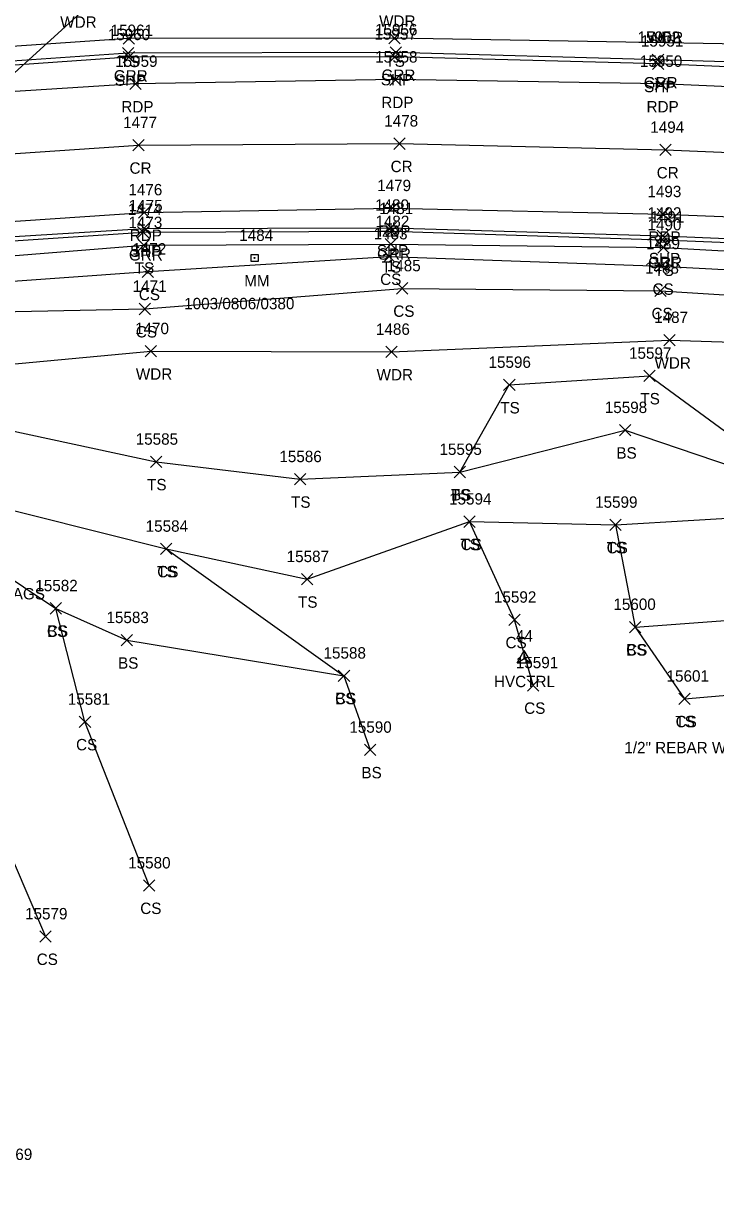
# Model space of a CAD drawing. Extents: x 1606530 to 1613020, y 784959 to 789666.
# Drawn here: x 1609266.7 to 1609388.2, y 788263.1 to 788467.6 of the extents above; entities that cross this region are included whole.
import ezdxf

# ---------------------------------------------------------------- set-up
doc = ezdxf.new("R2010")
doc.units = 0
for name, color, linetype in [('C_A', 7, 'Continuous'), ('C_I', 7, 'Continuous'), ('CPSM', 7, 'Continuous'), ('DCP', 7, 'Continuous'), ('L_A', 7, 'Continuous'), ('L_I', 7, 'Continuous'), ('L_TIC', 7, 'Continuous'), ('LAWA', 7, 'Continuous'), ('LELB', 7, 'Continuous'), ('M_C', 7, 'Continuous'), ('P_A', 7, 'Continuous'), ('P_I', 7, 'Continuous'), ('P_TIC', 7, 'Continuous'), ('PET', 7, 'Continuous'), ('PRC', 7, 'Continuous'), ('PSP', 7, 'Continuous'), ('R_A', 7, 'Continuous'), ('R_I', 7, 'Continuous'), ('R_TIC', 7, 'Continuous'), ('RGR', 7, 'Continuous'), ('S_A', 7, 'Continuous'), ('S_C', 7, 'Continuous'), ('S_I', 7, 'Continuous'), ('SRM', 7, 'Continuous')]:
    doc.layers.add(name, color=color, linetype=linetype)

msp = doc.modelspace()

# ---------------------------------------------------------------- linework, layer by layer
at = {"layer": 'CPSM'}
for p, q in [((1609353.34, 788355.35), (1609354.59, 788357.51)), ((1609355.84, 788355.35), (1609354.59, 788357.51)), ((1609354.59, 788356.07), (1609354.59, 788357.51)), ((1609353.34, 788355.35), (1609354.59, 788356.07)), ((1609353.34, 788355.35), (1609355.84, 788355.35)), ((1609354.59, 788356.07), (1609354.59, 788356.07)), ((1609354.59, 788356.07), (1609355.84, 788355.35))]:
    msp.add_line(p, q, dxfattribs=at)
at = {"layer": 'DCP'}
msp.add_lwpolyline([(1609180.84, 788382.35), (1609291.93, 788483.27)], dxfattribs=at)
at = {"layer": 'L_TIC'}
for points in [[(1609284.23, 788463.87), (1609286.23, 788465.87)], [(1609286.23, 788463.87), (1609284.23, 788465.87)], [(1609330.82, 788463.93), (1609332.82, 788465.93)], [(1609332.82, 788463.93), (1609330.82, 788465.93)], [(1609286.83, 788427.62), (1609288.83, 788429.62)], [(1609288.83, 788427.62), (1609286.83, 788429.62)], [(1609330.16, 788427.8), (1609332.16, 788429.8)], [(1609332.16, 788427.8), (1609330.16, 788429.8)], [(1609378, 788427.23), (1609380, 788429.23)], [(1609380, 788427.23), (1609378, 788429.23)], [(1609329.87, 788425.64), (1609331.87, 788427.64)], [(1609331.87, 788425.64), (1609329.87, 788427.64)], [(1609287.52, 788422.98), (1609289.52, 788424.98)], [(1609289.52, 788422.98), (1609287.52, 788424.98)], [(1609377.66, 788423.92), (1609379.66, 788425.92)], [(1609379.66, 788423.92), (1609377.66, 788425.92)], [(1609332.16, 788420.05), (1609334.16, 788422.05)], [(1609334.16, 788420.05), (1609332.16, 788422.05)], [(1609377.48, 788419.63), (1609379.48, 788421.63)], [(1609379.48, 788419.63), (1609377.48, 788421.63)], [(1609287, 788416.43), (1609289, 788418.43)], [(1609289, 788416.43), (1609287, 788418.43)], [(1609379.07, 788410.97), (1609381.07, 788412.97)], [(1609381.07, 788410.97), (1609379.07, 788412.97)], [(1609288.08, 788409.02), (1609290.08, 788411.02)], [(1609290.08, 788409.02), (1609288.08, 788411.02)], [(1609330.31, 788408.89), (1609332.31, 788410.89)], [(1609332.31, 788408.89), (1609330.31, 788410.89)], [(1609375.56, 788404.69), (1609377.56, 788406.69)], [(1609377.56, 788404.69), (1609375.56, 788406.69)], [(1609350.97, 788403.1), (1609352.97, 788405.1)], [(1609352.97, 788403.1), (1609350.97, 788405.1)], [(1609371.31, 788395.17), (1609373.31, 788397.17)], [(1609373.31, 788395.17), (1609371.31, 788397.17)], [(1609289, 788389.61), (1609291, 788391.61)], [(1609291, 788389.61), (1609289, 788391.61)], [(1609342.3, 788387.82), (1609344.3, 788389.82)], [(1609344.3, 788387.82), (1609342.3, 788389.82)], [(1609342.3, 788387.82), (1609344.3, 788389.82)], [(1609344.3, 788387.82), (1609342.3, 788389.82)], [(1609314.27, 788386.55), (1609316.27, 788388.55)], [(1609316.27, 788386.55), (1609314.27, 788388.55)], [(1609343.99, 788379.11), (1609345.99, 788381.11)], [(1609345.99, 788379.11), (1609343.99, 788381.11)], [(1609343.99, 788379.11), (1609345.99, 788381.11)], [(1609345.99, 788379.11), (1609343.99, 788381.11)], [(1609369.61, 788378.55), (1609371.61, 788380.55)], [(1609371.61, 788378.55), (1609369.61, 788380.55)], [(1609369.61, 788378.55), (1609371.61, 788380.55)], [(1609371.61, 788378.55), (1609369.61, 788380.55)], [(1609290.75, 788374.34), (1609292.75, 788376.34)], [(1609292.75, 788374.34), (1609290.75, 788376.34)], [(1609290.75, 788374.34), (1609292.75, 788376.34)], [(1609292.75, 788374.34), (1609290.75, 788376.34)], [(1609315.49, 788369.01), (1609317.49, 788371.01)], [(1609317.49, 788369.01), (1609315.49, 788371.01)], [(1609271.39, 788363.9), (1609273.39, 788365.9)], [(1609273.39, 788363.9), (1609271.39, 788365.9)], [(1609271.39, 788363.9), (1609273.39, 788365.9)], [(1609273.39, 788363.9), (1609271.39, 788365.9)], [(1609351.86, 788361.89), (1609353.86, 788363.89)], [(1609353.86, 788361.89), (1609351.86, 788363.89)], [(1609373.03, 788360.62), (1609375.03, 788362.62)], [(1609375.03, 788360.62), (1609373.03, 788362.62)], [(1609373.03, 788360.62), (1609375.03, 788362.62)], [(1609375.03, 788360.62), (1609373.03, 788362.62)], [(1609283.87, 788358.31), (1609285.87, 788360.31)], [(1609285.87, 788358.31), (1609283.87, 788360.31)], [(1609321.96, 788352.08), (1609323.96, 788354.08)], [(1609323.96, 788352.08), (1609321.96, 788354.08)], [(1609321.96, 788352.08), (1609323.96, 788354.08)], [(1609323.96, 788352.08), (1609321.96, 788354.08)], [(1609355.14, 788350.39), (1609357.14, 788352.39)], [(1609357.14, 788350.39), (1609355.14, 788352.39)], [(1609381.71, 788348.03), (1609383.71, 788350.03)], [(1609383.71, 788348.03), (1609381.71, 788350.03)], [(1609381.71, 788348.03), (1609383.71, 788350.03)], [(1609383.71, 788348.03), (1609381.71, 788350.03)], [(1609276.51, 788343.98), (1609278.51, 788345.98)], [(1609278.51, 788343.98), (1609276.51, 788345.98)], [(1609326.57, 788339.07), (1609328.57, 788341.07)], [(1609328.57, 788339.07), (1609326.57, 788341.07)], [(1609287.77, 788315.26), (1609289.77, 788317.26)], [(1609289.77, 788315.26), (1609287.77, 788317.26)], [(1609269.6, 788306.32), (1609271.6, 788308.32)], [(1609271.6, 788306.32), (1609269.6, 788308.32)]]:
    msp.add_lwpolyline(points, dxfattribs=at)
at = {"layer": 'LAWA'}
msp.add_lwpolyline([(1609030.56, 788292.64), (1609056.03, 788324.44), (1609082.56, 788354.61), (1609090.16, 788369.42), (1609097.26, 788381.32), (1609109.23, 788386.03), (1609115.48, 788389.16), (1609124.65, 788392.27), (1609168.82, 788397.24), (1609199.02, 788403.22), (1609247.62, 788406.18), (1609289.08, 788410.02), (1609331.31, 788409.89), (1609380.07, 788411.97), (1609422.47, 788410.64), (1609441.9, 788412.64), (1609456.94, 788393.19), (1609459.97, 788389.84), (1609451.94, 788379.3), (1609445.61, 788371.6)], dxfattribs=at)
at = {"layer": 'LELB'}
for points in [[(1609570.41, 788453.62), (1609564.76, 788453.01), (1609526.4, 788455.39), (1609486.04, 788457.71), (1609468.83, 788462.11), (1609453.21, 788464.39), (1609423.17, 788463.36), (1609331.82, 788464.93), (1609285.23, 788464.87), (1609232.95, 788461.35), (1609187.32, 788454.57)], [(1608830.7, 788263.06), (1608870.16, 788285.39), (1608903.61, 788303.66), (1608913.17, 788310.86), (1608944.69, 788327.51), (1608982.09, 788348.33), (1609025.65, 788367.84), (1609062.43, 788383.44), (1609080.36, 788388.45), (1609093.56, 788391.85), (1609111.49, 788398.34), (1609124.29, 788403.55), (1609165.33, 788413.89), (1609196.53, 788419.38), (1609241.91, 788424.94), (1609287.83, 788428.62), (1609331.16, 788428.8), (1609379, 788428.23), (1609424.69, 788425.72), (1609443.9, 788424.45), (1609475.84, 788418.57), (1609486.48, 788419.99), (1609502.63, 788421.7)], [(1609108.11, 788392.39), (1609124.69, 788397.48), (1609165.9, 788409.88), (1609197.34, 788410.75), (1609242.01, 788420.69), (1609288.52, 788423.98), (1609330.87, 788426.64), (1609378.66, 788424.92), (1609423.8, 788422.52), (1609442.79, 788421.03), (1609475.94, 788416.79), (1609485.22, 788416.48)], [(1609199.02, 788403.22), (1609245.4, 788416.55), (1609288, 788417.43), (1609333.16, 788421.05), (1609378.48, 788420.63), (1609422.35, 788417.84)], [(1609229.47, 788383.53), (1609235.87, 788391.77), (1609234.95, 788395.09), (1609256.53, 788397.81), (1609290, 788390.61), (1609315.27, 788387.55), (1609343.3, 788388.82), (1609351.97, 788404.1), (1609376.56, 788405.69), (1609392.36, 788394.13), (1609429.62, 788393.16), (1609442.68, 788388.57), (1609459.97, 788389.84), (1609474.42, 788390.35), (1609486.77, 788400.06), (1609484.73, 788410.56), (1609507.1, 788413.97), (1609507.85, 788418.71)], [(1609343.3, 788388.82), (1609372.31, 788396.17), (1609397.47, 788387.65), (1609429.62, 788393.16)], [(1609235.87, 788391.77), (1609256.08, 788384.31), (1609291.75, 788375.34), (1609316.49, 788370.01), (1609344.99, 788380.11), (1609370.61, 788379.55), (1609398.08, 788381.21), (1609428.47, 788380.83), (1609442.68, 788388.57)], [(1609222.59, 788380.4), (1609229.47, 788383.53), (1609244.73, 788362.88), (1609259.19, 788333.87), (1609270.6, 788307.32)], [(1609229.47, 788383.53), (1609255.52, 788376.15), (1609272.39, 788364.9), (1609284.87, 788359.31), (1609322.96, 788353.08), (1609327.57, 788340.07)], [(1609356.14, 788351.39), (1609352.86, 788362.89), (1609344.99, 788380.11)], [(1609370.61, 788379.55), (1609374.03, 788361.62), (1609382.71, 788349.03)], [(1609291.75, 788375.34), (1609322.96, 788353.08)], [(1609374.03, 788361.62), (1609409.62, 788364.21), (1609429.2, 788364.13), (1609464.94, 788364.57), (1609503.84, 788368.43), (1609529.95, 788369.13)], [(1609382.71, 788349.03), (1609409.78, 788351.37), (1609431.66, 788354.24), (1609466.67, 788360.22), (1609502.72, 788364.36), (1609529.95, 788369.13)], [(1609288.77, 788316.26), (1609277.51, 788344.98), (1609272.39, 788364.9)]]:
    msp.add_lwpolyline(points, dxfattribs=at)
at = {"layer": 'P_TIC'}
for points in [[(1609284.23, 788460.6), (1609286.23, 788462.6)], [(1609286.23, 788460.6), (1609284.23, 788462.6)], [(1609330.88, 788460.68), (1609332.88, 788462.68)], [(1609332.88, 788460.68), (1609330.88, 788462.68)], [(1609377.09, 788459.47), (1609379.09, 788461.47)], [(1609379.09, 788459.47), (1609377.09, 788461.47)], [(1609285.4, 788455.92), (1609287.4, 788457.92)], [(1609287.4, 788455.92), (1609285.4, 788457.92)], [(1609331.01, 788456.67), (1609333.01, 788458.67)], [(1609333.01, 788456.67), (1609331.01, 788458.67)], [(1609377.56, 788455.92), (1609379.56, 788457.92)], [(1609379.56, 788455.92), (1609377.56, 788457.92)], [(1609285.9, 788445.16), (1609287.9, 788447.16)], [(1609287.9, 788445.16), (1609285.9, 788447.16)], [(1609331.71, 788445.44), (1609333.71, 788447.44)], [(1609333.71, 788445.44), (1609331.71, 788447.44)], [(1609378.39, 788444.34), (1609380.39, 788446.34)], [(1609380.39, 788444.34), (1609378.39, 788446.34)], [(1609286.88, 788433.37), (1609288.88, 788435.37)], [(1609288.88, 788433.37), (1609286.88, 788435.37)], [(1609330.48, 788434.11), (1609332.48, 788436.11)], [(1609332.48, 788434.11), (1609330.48, 788436.11)], [(1609377.89, 788433.05), (1609379.89, 788435.05)], [(1609379.89, 788433.05), (1609377.89, 788435.05)], [(1609286.88, 788430.58), (1609288.88, 788432.58)], [(1609288.88, 788430.58), (1609286.88, 788432.58)], [(1609330.2, 788430.67), (1609332.2, 788432.67)], [(1609332.2, 788430.67), (1609330.2, 788432.67)], [(1609377.92, 788429.28), (1609379.92, 788431.28)], [(1609379.92, 788429.28), (1609377.92, 788431.28)]]:
    msp.add_lwpolyline(points, dxfattribs=at)
at = {"layer": 'PET'}
for points in [[(1609713.17, 788438.63), (1609680.93, 788440.45), (1609652, 788442.02), (1609625.85, 788443.73), (1609580.96, 788446.42), (1609565.08, 788447.47), (1609525.71, 788449.46), (1609486.16, 788451.54), (1609451.91, 788453.58), (1609423.87, 788454.94), (1609378.56, 788456.92), (1609332.01, 788457.67), (1609286.4, 788456.92), (1609233.03, 788453.52), (1609189.08, 788447.38), (1609175.76, 788445.19), (1609148.78, 788440), (1609127.71, 788434.8)], [(1608827.2, 788266.24), (1608867.86, 788290.54), (1608906.68, 788312.86), (1608942.68, 788332.75), (1608980.54, 788352.16), (1609023.57, 788373.22), (1609061.44, 788389.9), (1609090.8, 788401.17), (1609121.92, 788410.09), (1609165.17, 788420), (1609195.85, 788425.54), (1609240.14, 788431.13), (1609287.88, 788434.37), (1609331.48, 788435.11), (1609378.89, 788434.05), (1609425.43, 788432.25), (1609443.83, 788431.33), (1609477.32, 788429.78), (1609518.44, 788427.6), (1609569.18, 788424.68), (1609602.99, 788422.58), (1609641.45, 788420.37), (1609681.7, 788417.92), (1609727.38, 788415.53)]]:
    msp.add_lwpolyline(points, dxfattribs=at)
at = {"layer": 'PRC'}
msp.add_lwpolyline([(1608863.25, 788300.9), (1608901.81, 788322.6), (1608937.61, 788342.72), (1608976.12, 788362.76), (1609017.58, 788382.95), (1609062.58, 788402.24), (1609089.79, 788412.89), (1609118.81, 788421.44), (1609162.84, 788431.75), (1609194.15, 788437.36), (1609237.64, 788442.85), (1609286.9, 788446.16), (1609332.71, 788446.44), (1609379.39, 788445.34), (1609425.62, 788443.43), (1609445.83, 788442.47), (1609477.78, 788440.95), (1609519.76, 788438.85), (1609569.72, 788435.9), (1609601.73, 788434.31), (1609642.39, 788431.82), (1609682.03, 788429.15), (1609726.55, 788426.79)], dxfattribs=at)
at = {"layer": 'PSP'}
for points in [[(1609713.92, 788443.12), (1609681.22, 788444.65), (1609658, 788445.99), (1609646.32, 788446.92), (1609626.34, 788447.99), (1609592.68, 788450.1), (1609566.9, 788451.27), (1609526.22, 788453.59), (1609486.02, 788455.2), (1609451.52, 788457.02), (1609423.82, 788458.46), (1609378.09, 788460.47), (1609331.88, 788461.68), (1609285.23, 788461.6), (1609232.6, 788457.92), (1609188.51, 788451.36), (1609172.5, 788448.52), (1609147.32, 788443.74), (1609126.97, 788439.13), (1609114.12, 788436.45)], [(1608830.36, 788265), (1608869.22, 788287.4), (1608908.59, 788309.54), (1608943.86, 788329.41), (1608981.49, 788349.27), (1609025.12, 788370.21), (1609061.92, 788386.23), (1609076.39, 788391.44), (1609089.96, 788397.16), (1609122.92, 788407.13), (1609165.71, 788417.03), (1609196.42, 788422.44), (1609241.31, 788428.68), (1609287.88, 788431.58), (1609331.2, 788431.67), (1609378.92, 788430.28), (1609425.01, 788428.31)]]:
    msp.add_lwpolyline(points, dxfattribs=at)
at = {"layer": 'R_TIC'}
for points in [[(1609284.08, 788461.33), (1609286.08, 788463.33)], [(1609286.08, 788461.33), (1609284.08, 788463.33)], [(1609331.06, 788461.45), (1609333.06, 788463.45)], [(1609333.06, 788461.45), (1609331.06, 788463.45)], [(1609377.06, 788460.13), (1609379.06, 788462.13)], [(1609379.06, 788460.13), (1609377.06, 788462.13)], [(1609286.73, 788429.93), (1609288.73, 788431.93)], [(1609288.73, 788429.93), (1609286.73, 788431.93)], [(1609330.28, 788430.08), (1609332.28, 788432.08)], [(1609332.28, 788430.08), (1609330.28, 788432.08)], [(1609377.86, 788428.59), (1609379.86, 788430.59)], [(1609379.86, 788428.59), (1609377.86, 788430.59)]]:
    msp.add_lwpolyline(points, dxfattribs=at)
at = {"layer": 'RGR'}
for points in [[(1609451.62, 788460.78), (1609423.64, 788459.82), (1609378.06, 788461.13), (1609332.06, 788462.45), (1609285.08, 788462.33), (1609232.47, 788458.7), (1609188.44, 788451.91), (1609171.83, 788449.19), (1609146.47, 788445.79), (1609126.98, 788443.62)], [(1609093.56, 788395.55), (1609123.33, 788406.23), (1609196.19, 788421.65), (1609241.24, 788427.81), (1609287.73, 788430.93), (1609331.28, 788431.08), (1609378.86, 788429.59), (1609425.05, 788427.72), (1609442.61, 788426.23), (1609477.2, 788421.48)]]:
    msp.add_lwpolyline(points, dxfattribs=at)
at = {"layer": 'SRM'}
msp.add_lwpolyline([(1609306.65, 788427), (1609307.9, 788427), (1609307.9, 788425.75), (1609306.65, 788425.75)], close=True, dxfattribs=at)
msp.add_circle((1609307.27, 788426.38), 0.0833, dxfattribs=at)

# ---------------------------------------------------------------- texts
at = {"layer": 'C_A'}
msp.add_text('HVCTRL', height=2, dxfattribs=at).set_placement((1609349.28, 788351.07))
at = {"layer": 'C_I'}
msp.add_text('44', height=2, dxfattribs=at).set_placement((1609353.13, 788359.07))
at = {"layer": 'L_A'}
for s, p in [('WDR', (1609273.17, 788466.77)), ('WDR', (1609329.12, 788466.95)), ('WDR', (1609376.1, 788464.08)), ('TS', (1609283.64, 788459.87)), ('TS', (1609330.23, 788459.93)), ('TS', (1609286.24, 788423.62)), ('TS', (1609329.57, 788423.8)), ('TS', (1609377.41, 788423.23)), ('CS', (1609329.31, 788421.64)), ('CS', (1609286.96, 788418.98)), ('CS', (1609377.1, 788419.92)), ('CS', (1609331.61, 788416.05)), ('CS', (1609376.92, 788415.63)), ('CS', (1609286.44, 788412.43)), ('WDR', (1609377.44, 788406.97)), ('WDR', (1609286.44, 788405.02)), ('WDR', (1609328.68, 788404.89)), ('TS', (1609374.97, 788400.69)), ('TS', (1609350.38, 788399.1)), ('BS', (1609370.75, 788391.17)), ('TS', (1609288.41, 788385.61)), ('TS', (1609341.71, 788383.82)), ('BS', (1609341.74, 788383.82)), ('TS', (1609313.67, 788382.55)), ('TS', (1609343.4, 788375.11)), ('CS', (1609343.43, 788375.11)), ('TS', (1609369.02, 788374.55)), ('CS', (1609369.05, 788374.55)), ('TS', (1609290.16, 788370.34)), ('CS', (1609290.19, 788370.34)), ('TS', (1609314.9, 788365.01)), ('CS', (1609270.84, 788359.9)), ('BS', (1609270.84, 788359.9)), ('CS', (1609351.3, 788357.89)), ('CS', (1609372.47, 788356.62)), ('BS', (1609372.47, 788356.62)), ('BS', (1609283.31, 788354.31)), ('CS', (1609321.4, 788348.08)), ('BS', (1609321.4, 788348.08)), ('CS', (1609354.58, 788346.39)), ('TS', (1609381.12, 788344.03)), ('CS', (1609381.15, 788344.03)), ('CS', (1609275.95, 788339.98)), ('BS', (1609326.02, 788335.07)), ('CS', (1609287.21, 788311.26)), ('CS', (1609269.04, 788302.32))]:
    msp.add_text(s, height=2, dxfattribs=at).set_placement(p)
at = {"layer": 'L_I'}
for s, p in [('1473', (1609285.13, 788431.62)), ('1482', (1609328.47, 788431.8)), ('1490', (1609376.22, 788431.23)), ('1483', (1609328.17, 788429.64)), ('1472', (1609285.82, 788426.98)), ('1489', (1609375.96, 788427.92)), ('1485', (1609330.47, 788424.05)), ('1488', (1609375.78, 788423.63)), ('1471', (1609285.88, 788420.43)), ('1487', (1609377.38, 788414.97)), ('1470', (1609286.3, 788413.02)), ('1486', (1609328.57, 788412.89)), ('15597', (1609372.97, 788408.69)), ('15596', (1609348.32, 788407.1)), ('15598', (1609368.72, 788399.17)), ('15585', (1609286.41, 788393.61)), ('15595', (1609339.71, 788391.82)), ('15595', (1609339.71, 788391.82)), ('15586', (1609311.62, 788390.55)), ('15594', (1609341.4, 788383.11)), ('15594', (1609341.4, 788383.11)), ('15599', (1609367.02, 788382.55)), ('15599', (1609367.02, 788382.55)), ('15584', (1609288.16, 788378.34)), ('15584', (1609288.16, 788378.34)), ('15587', (1609312.9, 788373.01)), ('15582', (1609268.8, 788367.9)), ('15582', (1609268.8, 788367.9)), ('15592', (1609349.27, 788365.89)), ('15600', (1609370.23, 788364.62)), ('15600', (1609370.23, 788364.62)), ('15583', (1609281.28, 788362.31)), ('15588', (1609319.37, 788356.08)), ('15588', (1609319.37, 788356.08)), ('15591', (1609353.11, 788354.39)), ('15601', (1609379.56, 788352.03)), ('15601', (1609379.56, 788352.03)), ('15581', (1609274.49, 788347.98)), ('15590', (1609323.9, 788343.07)), ('15580', (1609285.09, 788319.26)), ('15579', (1609267, 788310.32)), ('15569', (1609260.83, 788268.1))]:
    msp.add_text(s, height=2, dxfattribs=at).set_placement(p)
at = {"layer": 'M_C'}
for s, p in [('4"X4" CONC W/ REBAR 6" AGS', (1609231.68, 788366.47)), ('1/2" REBAR W/ CAP PEATMAN LS', (1609372.15, 788339.46))]:
    msp.add_text(s, height=2, dxfattribs=at).set_placement(p)
at = {"layer": 'P_A'}
for s, p in [('SHP', (1609282.76, 788456.6)), ('SHP', (1609329.42, 788456.68)), ('SHP', (1609375.62, 788455.47)), ('RDP', (1609283.89, 788451.92)), ('RDP', (1609329.5, 788452.67)), ('RDP', (1609376.05, 788451.92)), ('CR', (1609285.33, 788441.16)), ('CR', (1609331.14, 788441.44)), ('CR', (1609377.83, 788440.34)), ('RDP', (1609285.37, 788429.37)), ('RDP', (1609328.97, 788430.11)), ('RDP', (1609376.38, 788429.05)), ('SHP', (1609285.41, 788426.58)), ('SHP', (1609328.73, 788426.67)), ('SHP', (1609376.45, 788425.28))]:
    msp.add_text(s, height=2, dxfattribs=at).set_placement(p)
at = {"layer": 'P_I'}
for s, p in [('15960', (1609281.51, 788464.6)), ('15957', (1609328.29, 788464.68)), ('15951', (1609375.06, 788463.47)), ('15959', (1609282.8, 788459.92)), ('15958', (1609328.42, 788460.67)), ('15950', (1609374.88, 788459.92)), ('1477', (1609284.2, 788449.16)), ('1478', (1609330.02, 788449.44)), ('1494', (1609376.7, 788448.34)), ('1476', (1609285.13, 788437.37)), ('1479', (1609328.78, 788438.11)), ('1493', (1609376.2, 788437.05)), ('1475', (1609285.18, 788434.58)), ('1480', (1609328.42, 788434.67)), ('1492', (1609376.22, 788433.28))]:
    msp.add_text(s, height=2, dxfattribs=at).set_placement(p)
at = {"layer": 'R_A'}
for p in [(1609282.57, 788457.33), (1609329.55, 788457.45), (1609375.55, 788456.13), (1609285.22, 788425.93), (1609328.77, 788426.08), (1609376.34, 788424.59)]:
    msp.add_text('GRR', height=2, dxfattribs=at).set_placement(p)
at = {"layer": 'R_I'}
for s, p in [('15961', (1609282.01, 788465.33)), ('15956', (1609328.41, 788465.45)), ('15952', (1609374.47, 788464.13)), ('1474', (1609285.03, 788433.93)), ('1481', (1609329.16, 788434.08)), ('1491', (1609376.73, 788432.59))]:
    msp.add_text(s, height=2, dxfattribs=at).set_placement(p)
at = {"layer": 'S_A'}
msp.add_text('MM', height=2, dxfattribs=at).set_placement((1609305.46, 788421.38))
at = {"layer": 'S_C'}
msp.add_text('1003/0806/0380', height=2, dxfattribs=at).set_placement((1609294.92, 788417.38))
at = {"layer": 'S_I'}
msp.add_text('1484', height=2, dxfattribs=at).set_placement((1609304.58, 788429.38))

doc.saveas('drawing.dxf')
